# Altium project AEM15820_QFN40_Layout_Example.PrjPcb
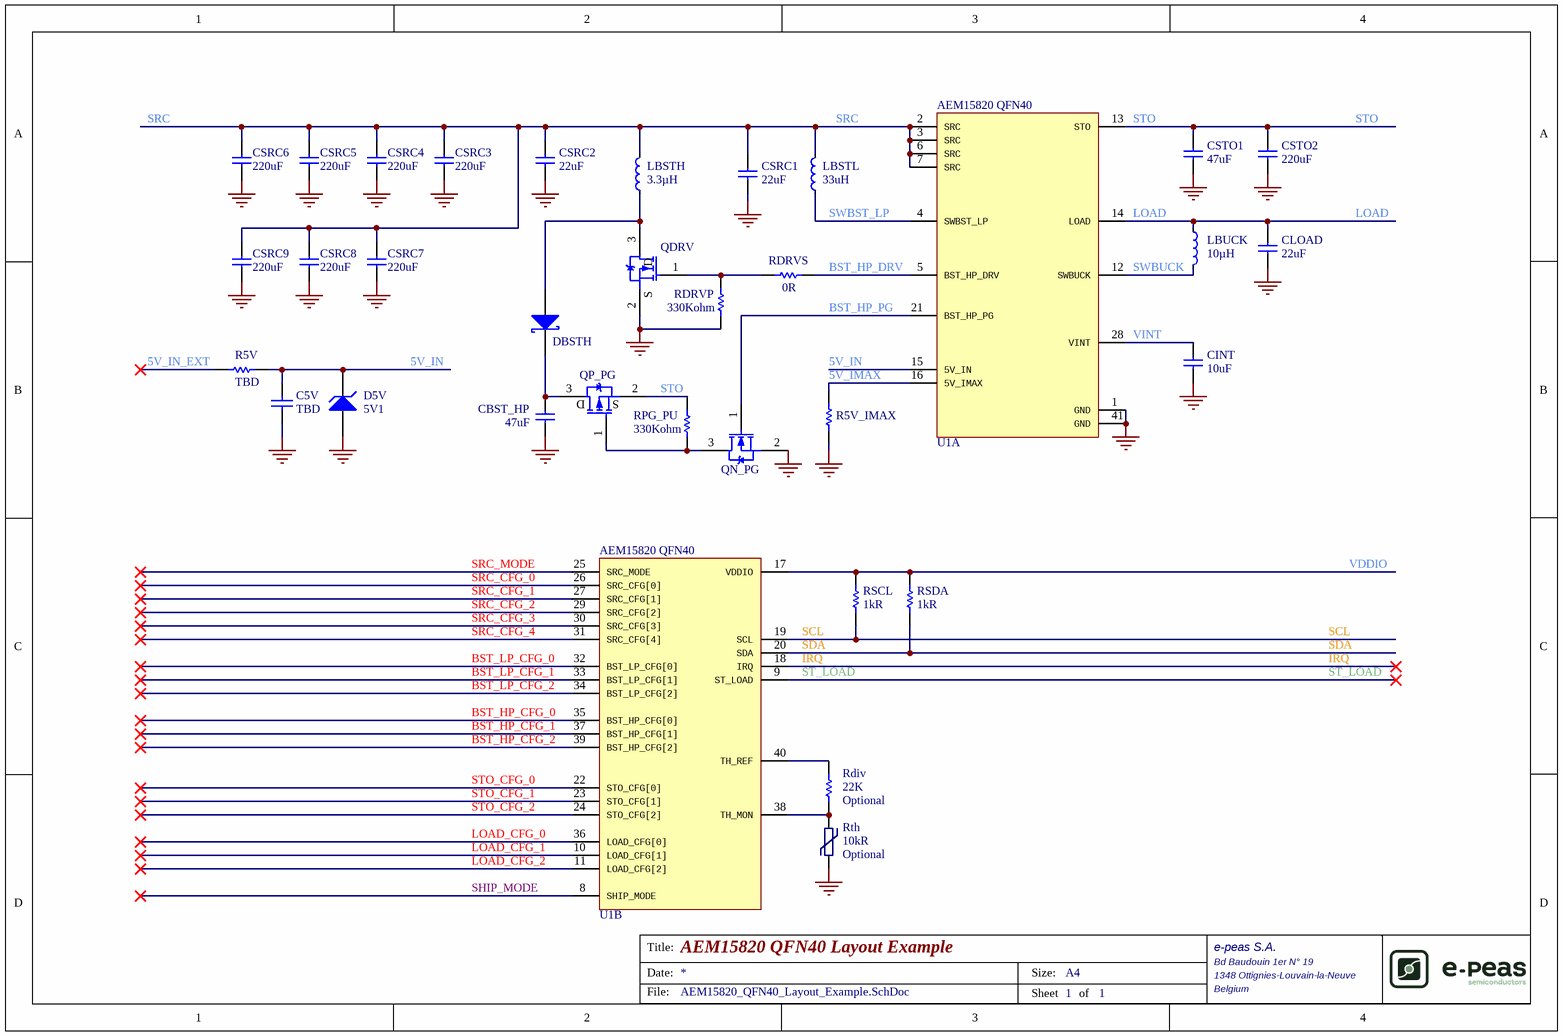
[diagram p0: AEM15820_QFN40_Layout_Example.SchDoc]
Address1_Global: Bd Baudouin 1er N° 19; Address2_Global: 1348 Ottignies-Louvain-la-Neuve; Address3_Global: Belgium; Name: AEM15820 QFN40 Layout Example; Organization_Global: e-peas S.A.; Website_Global: https://e-peas.com
1 sheet, 33 parts. Net scope: global (net labels, ports and power ports of the same name join across sheets).
Board file: AEM15820_QFN40_Layout_Example.PcbDoc

## Sheet AEM15820_QFN40_Layout_Example.SchDoc
size A4; DocumentNumber: 1; SheetNumber: 1; SheetTotal: 1; Organization: e-peas S.A.; Address1: The Gate Business Center; Address2: rue Cattelain 1 b4,; Address3: 1435 Mont-St-Guibert; Address4: Belgium

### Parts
C5V  value TBD  [C0603_[1608]]  (hidden comment: Cap Ceramic 0603 TBD)
CBST_HP  47uF  [C0603_[1608]]
CINT  10uF  [C0402_[1005]]
CLOAD  22uF  [C0603_[1608]]
CSRC1  22uF  [C0603_[1608]]
CSRC2  22uF  [C0603_[1608]]
CSRC3  220uF  [C1206_[3216]]
CSRC4  220uF  [C1206_[3216]]
CSRC5  220uF  [C1206_[3216]]
CSRC6  220uF  [C1206_[3216]]
CSRC7  220uF  [C1206_[3216]]
CSRC8  220uF  [C1206_[3216]]
CSRC9  220uF  [C1206_[3216]]
CSTO1  47uF  [C0603_[1608]]
CSTO2  220uF  [C1206_[3216]]
D5V  5V1  [SOT23-3P  3x1.40mm Pitch=0.915mm diode AK]
DBSTH  Schottky_Generic  [DO-214AA]  (value not drawn)
LBSTH  3.3µH  [Wurth_MAPI_5030]
LBSTL  33uH  [Coilcraft-LPS4018]
LBUCK  10µH  [Inductor_VLS252012]
QDRV  MOSFETs Nch 30V 10A Si MOSFET  [Powerpak SC70]  (value not drawn)
QN_PG  MOSFET Canal N, 60 V, 230 mA, 2.2 ohm, Vgsth 1.4V max, low leakage  [SOT23-3L_STM-L]  (value not drawn)
QP_PG  MOSFET P-CH 20V 70A 6.5 mOhms @ 2.5V  [PowerDI3333-8]  (value not drawn)
R5V  TBD  [Resistor_0603_[1608]]
R5V_IMAX  TBD  [Resistor_0603_[1608]]  (value not drawn)
Rdiv  22K  [Resistor_0402]
RDRVP  330Kohm  [Resistor_0603_[1608]]
RDRVS  0R  [Resistor_0402]
RPG_PU  330Kohm  [Resistor_0603_[1608]]
RSCL  1kR  [Resistor_0603_[1608]]
RSDA  1kR  [Resistor_0603_[1608]]
Rth  10kR  [Resistor_0402]
U1  AEM15820_QFN40  [QFN40_5x5mm_pitch0.4mm_ASE_98A0040QN185]  (value not drawn)  (parts A,B of 2)

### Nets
GND: C5V.1 CBST_HP.1 CINT.1 CLOAD.1 CSRC1.1 CSRC2.1 CSRC3.1 CSRC4.1 CSRC5.1 CSRC6.1 CSRC7.1 CSRC8.1 CSRC9.1 CSTO1.1 CSTO2.1 D5V.A QDRV.2(S) QN_PG.2(S12) R5V_IMAX.1 RDRVP.1 Rth.1 U1.1(GND) U1.41(GND)
5V_IMAX: R5V_IMAX.2 U1.16(5V_IMAX)
5V_IN: C5V.2 D5V.K R5V.2 U1.15(5V_IN)
5V_IN_EXT: R5V.1
BST_HP_CFG_0: U1.35(BST_HP_CFG[0])
BST_HP_CFG_1: U1.37(BST_HP_CFG[1])
BST_HP_CFG_2: U1.39(BST_HP_CFG[2])
BST_HP_DRV: RDRVS.2 U1.5(BST_HP_DRV)
BST_HP_PG: QN_PG.1(G1) U1.21(BST_HP_PG)
BST_LP_CFG_0: U1.32(BST_LP_CFG[0])
BST_LP_CFG_1: U1.33(BST_LP_CFG[1])
BST_LP_CFG_2: U1.34(BST_LP_CFG[2])
IRQ: U1.18(IRQ)
LOAD: CLOAD.2 LBUCK.1 U1.14(LOAD)
LOAD_CFG_0: U1.36(LOAD_CFG[0])
LOAD_CFG_1: U1.10(LOAD_CFG[1])
LOAD_CFG_2: U1.11(LOAD_CFG[2])
SCL: RSCL.1 U1.19(SCL)
SDA: RSDA.1 U1.20(SDA)
SHIP_MODE: U1.8(SHIP_MODE)
SRC: CSRC1.2 CSRC2.2 CSRC3.2 CSRC4.2 CSRC5.2 CSRC6.2 CSRC7.2 CSRC8.2 CSRC9.2 LBSTH.2 LBSTL.2 U1.2(SRC) U1.3(SRC) U1.6(SRC) U1.7(SRC)
SRC_CFG_0: U1.26(SRC_CFG[0])
SRC_CFG_1: U1.27(SRC_CFG[1])
SRC_CFG_2: U1.29(SRC_CFG[2])
SRC_CFG_3: U1.30(SRC_CFG[3])
SRC_CFG_4: U1.31(SRC_CFG[4])
SRC_MODE: U1.25(SRC_MODE)
ST_LOAD: U1.9(ST_LOAD)
STO: CSTO1.2 CSTO2.2 QP_PG.2(S) RPG_PU.2 U1.13(STO)
STO_CFG_0: U1.22(STO_CFG[0])
STO_CFG_1: U1.23(STO_CFG[1])
STO_CFG_2: U1.24(STO_CFG[2])
SWBST_LP: LBSTL.1 U1.4(SWBST_LP)
SWBUCK: LBUCK.2 U1.12(SWBUCK)
VDDIO: RSCL.2 RSDA.2 U1.17(VDDIO)
VINT: CINT.2 U1.28(VINT)
NetCBST_HP_2: CBST_HP.2 DBSTH.K QP_PG.3(D)
NetDBSTH_A: DBSTH.A LBSTH.1 QDRV.3(D)
NetQDRV_1: QDRV.1(G) RDRVP.2 RDRVS.1
NetQN_PG_3: QN_PG.3(D1) QP_PG.1(G) RPG_PU.1
NetRdiv_1: Rdiv.1 Rth.2 U1.38(TH_MON)
NetRdiv_2: Rdiv.2 U1.40(TH_REF)

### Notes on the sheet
- (near Rdiv) Optional
- (near Rth) Optional
- (near U1) Title:
- Date:
- Size:
- A4
- File:
- Sheet
- of

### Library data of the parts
C5V = Cap Ceramic 0603 TBD: Package Metric: 1608
CBST_HP CSTO1 = Cap Ceramic 47uF 6.3V +/-20% X5R 0603: Manuf: Murata; Manuf PN: GRM188R60J476ME15D; Package Metric: 1608
CINT = Cap Ceramic 10uF, 6.3V, 20%, X5R, 0402: Manuf: MURATA; Manuf PN: GRM155R60J106ME05D; Package Metric: 1005
CLOAD CSRC1 CSRC2 = Cap Ceramic 22uF, 10V, 20%, X5R 0603: Manuf: MuRata; Manuf PN: GRM188R61A226ME15D; Package Metric: 1608
CSRC3-CSRC9 CSTO2 = Cap Ceramic 220uF, 6.3V, 20%, X5R: Manuf: Murata; Manuf PN: GRM31CR60J227ME11L; Package Metric: 3216
D5V = Zener 5.1V 350mW BZX84C5V1-TP: Zener Diode 5.1 V 350 mW ±5% Surface Mount SOT-23; Manuf: Micro Commercial Co; Vbr: 5.1V; I continous: 68mA
DBSTH = Schottky Rectifier - VS-10BQ015HM3/5BT: Schottky Rectifier, 15 V, 1 A, Single, DO-214AA (SMB), 2 Pins, 330 mV; Manuf: Vishay; I continous: 1A
LBSTH = Power Inductor, 3.3 µH, 6.2 A, Shielded, 7.3 A, WE-MAPI: Power Inductor (SMD), 3.3 µH, 6.2 A, Shielded, 7.3 A, WE-MAPI; Manuf: Wurth; Manuf PN: 74438367033; Tol: 20%; Rdc: 23mOhms; Self Resonant Frequency: 22MHz; Max DC Current: 8
LBSTL = Power Inductor 33uH - 0.68A - LPS4018 - Small Symbol: Power Inductor 33uH - 0,68A - LPS4018; Manuf: Coilcraft; Manuf PN: LPS4018-333MRB; Tol: 20%; Rdc: 420mOhms; Self Resonant Frequency: 20MHz; Max DC Current: 800mA
LBUCK = Power Inductor 10uH - 1008 - VLS252012CX: Power Inductor 10µH - 2520 - VLS252012CX; Manuf: TDK; Manuf PN: VLS252012CX-100M-1; Tol: ±20%; Rdc: 0.402 ohm; Max DC Current: 790 mA; Package Metric: 2520
QDRV = RF4E100AJTCR: Manuf: ROHM; Mtn: SMD
QN_PG = BSS138NH6327XTSA2 N-MOSFET (Low Leakage): Manuf: INFINEON; Mtn: SMD; VGS Max (V): 20; VGS(th) Max (V): 1.4; Channel Polarity: N Channel; Configuration: Single
QP_PG = DMP2005UFG - P-MOS 20V 70A 6.5 mOhms @ 2.5V: Manuf: Diodes Inc.; Manuf PN: DMP2005UFG-13; Mtn: SMD
R5V R5V_IMAX = Resistor TBD - 0603: Mnt: SMD
Rdiv = Resistor 22KR - 0402 - 50V: Manuf: Yageo; Manuf PN: RC0402FR-0722KL; P max mW: 63; Tol %: 1%; Mnt: SMD
RDRVP RPG_PU = Resistor 330Kohm 0603: Manuf: Yageo; Manuf PN: RC0603FR-07330KL; P max mW: 100; Tol %: 1%; V max: 75V; Mnt: SMD; Package Metric: 1608
RDRVS = Resistor 0R - 0402 - 50V - Thin_Film: Manuf: VISHAY; Manuf PN: MCS04020Z0000ZE000; Mnt: SMD; P max mW: 100mW; Package Metric: 1005; V max: 50
RSCL RSDA = Resistor 1kOhm - 0603 - 75V - 1%: Manuf: Multicomp; Manuf PN: MCWR06X1001FTL; P max mW: 100mW; Tol %: 1; Mnt: SMD; Package Metric: 1608
Rth = Thermistor 10kR CTN 0402: Manuf: Murata; Manuf PN: NCP15XH103J03RC; Mnt: SMD
U1 = AEM15820 QFN40: Manuf: e-peas; Manuf PN: 10AEM15820J0000; Mnt: SMD; Pitch: 0.4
